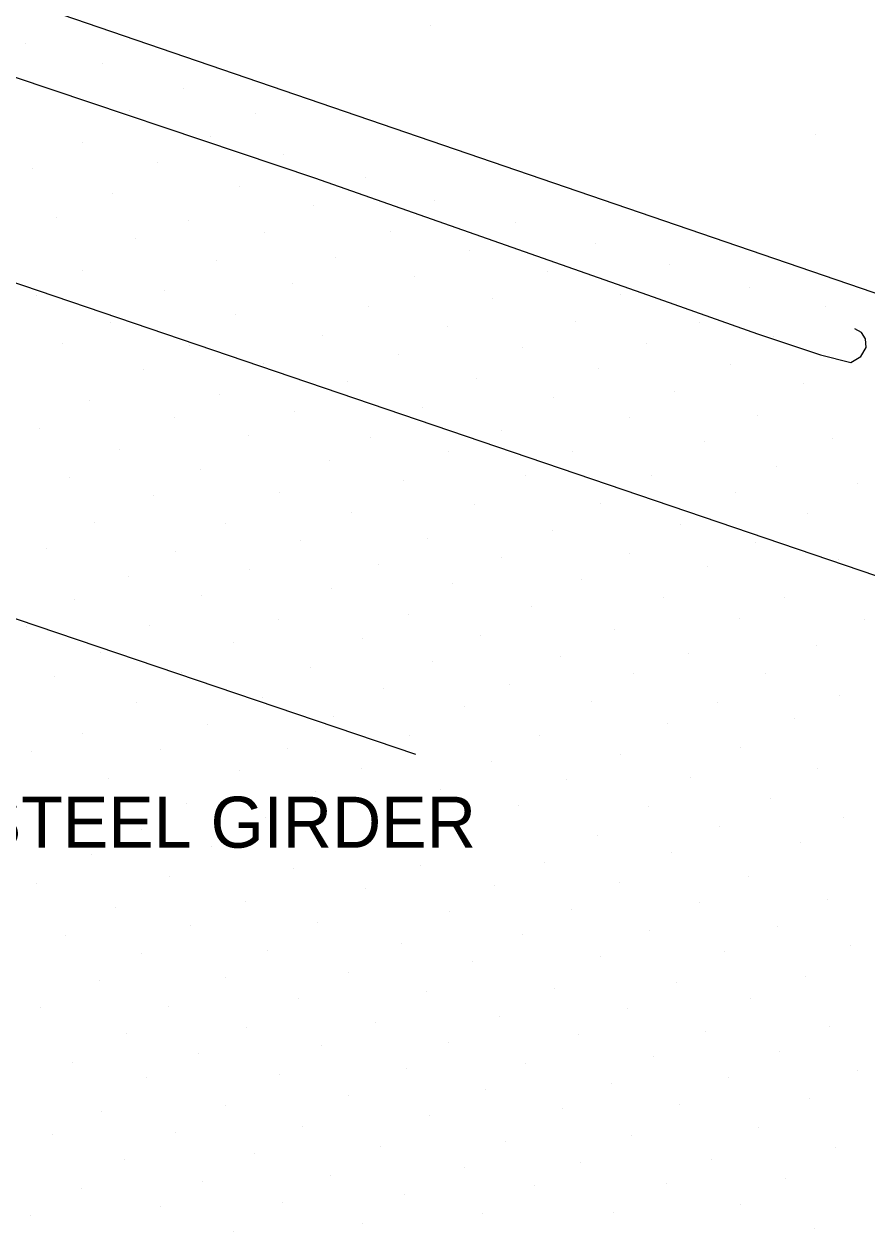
# Model space of a CAD drawing. Extents: x 1733582 to 1734070, y 467256 to 468256.
# Drawn here: x 1733864.11 to 1733893.84, y 467694.29 to 467736.94 of the extents above; entities that cross this region are included whole.
import ezdxf

# ---------------------------------------------------------------- set-up
doc = ezdxf.new("R2010")
doc.units = 0
for name, color, linetype in [('Default', 7, 'Continuous'), ('S_Ground_SpotElevation', 7, 'Continuous'), ('S_Guardrail_Beam', 7, 'Continuous'), ('S_Roadway_Edge_Pavement', 7, 'Continuous'), ('S_Roadway_Painted_Lines', 7, 'Continuous'), ('S_Text', 7, 'Continuous')]:
    doc.layers.add(name, color=color, linetype=linetype)

# ---------------------------------------------------------------- blocks, each defined once
blk = doc.blocks.new('POINT_DISPLAY')
at = {"layer": 'Default'}
blk.add_line((0, 0), (0, 0), dxfattribs=at)

msp = doc.modelspace()

# ---------------------------------------------------------------- linework, layer by layer
at = {"layer": 'S_Guardrail_Beam'}
msp.add_lwpolyline([(1733779.584, 467763.162), (1733791.412, 467759.266), (1733803.188, 467755.466), (1733815.088, 467751.54), (1733826.834, 467747.566), (1733839.025, 467743.476), (1733850.692, 467739.538), (1733862.451, 467735.523), (1733874.35, 467731.517), (1733886.109, 467727.39), (1733889.984, 467726.018), (1733892.208, 467725.279), (1733893.28, 467725.008), (1733893.637, 467725.214), (1733893.817, 467725.531), (1733893.796, 467725.839), (1733893.658, 467726.063), (1733893.419, 467726.195)], dxfattribs=at)
at = {"layer": 'S_Roadway_Edge_Pavement'}
msp.add_lwpolyline([(1734047.514, 467668.647), (1734012.708, 467681.197), (1733935.599, 467708.176), (1733908.807, 467722.422), (1733806.077, 467757.609), (1733715.329, 467786.896), (1733665.166, 467802.478), (1733604.388, 467822.173)], dxfattribs=at)
at = {"layer": 'S_Roadway_Painted_Lines'}
msp.add_line((1733862.631, 467716.356), (1733877.917, 467711.182), dxfattribs=at)
msp.add_lwpolyline([(1733600.615, 467812.285), (1733624.074, 467805.253), (1733650.091, 467797.478), (1733690.162, 467785.254), (1733709.513, 467779.192), (1733740.833, 467769.059), (1733764.442, 467761.384), (1733801.856, 467748.917), (1733825.1, 467741.003), (1733865.745, 467727.157), (1733942.114, 467701.157), (1734018.088, 467674.904), (1734046.328, 467664.849)], dxfattribs=at)

# ---------------------------------------------------------------- block references
at = {"layer": 'S_Ground_SpotElevation'}
for p in [(1733878.445, 467736.911), (1733864.142, 467736.245), (1733866.862, 467735.573), (1733869.723, 467734.67), (1733865.111, 467734.612), (1733867.837, 467733.88), (1733872.259, 467733.794), (1733870.681, 467732.986), (1733892.047, 467733.039), (1733866.165, 467732.756), (1733873.275, 467732.34), (1733864.402, 467731.852), (1733868.806, 467732.051), (1733876.138, 467731.541), (1733867.229, 467730.972), (1733871.722, 467731.199), (1733874.322, 467730.528), (1733878.578, 467730.719), (1733865.24, 467730.136), (1733869.903, 467730.024), (1733872.601, 467729.592), (1733877.033, 467729.637), (1733881.444, 467729.947), (1733868.044, 467729.391), (1733884.279, 467729.21), (1733875.11, 467728.692), (1733879.826, 467728.953), (1733870.879, 467728.612), (1733886.89, 467728.469), (1733866.184, 467728.237), (1733877.875, 467728.048), (1733882.563, 467728.212), (1733869.068, 467727.529), (1733873.562, 467727.786), (1733885.168, 467727.408), (1733889.688, 467727.659), (1733864.538, 467727.365), (1733876.272, 467726.984), (1733880.648, 467727.245), (1733892.376, 467726.977), (1733871.58, 467726.696), (1733867.16, 467726.427), (1733879.054, 467726.285), (1733883.581, 467726.456), (1733887.95, 467726.425), (1733874.651, 467725.966), (1733890.556, 467725.928), (1733865.461, 467725.688), (1733869.952, 467725.618), (1733877.32, 467725.289), (1733881.71, 467725.519), (1733886.07, 467725.683), (1733872.563, 467724.964), (1733889.037, 467724.921), (1733893.476, 467725.128), (1733868.327, 467724.774), (1733880.086, 467724.433), (1733884.359, 467724.804), (1733875.504, 467724.317), (1733891.613, 467724.263), (1733866.398, 467723.65), (1733870.989, 467723.873), (1733882.8, 467723.77), (1733887.05, 467723.971), (1733873.664, 467723.277), (1733878.162, 467723.404), (1733869.404, 467723.058), (1733885.452, 467723.062), (1733889.976, 467723.119), (1733864.653, 467722.688), (1733872.036, 467722.427), (1733876.321, 467722.37), (1733880.945, 467722.618), (1733892.638, 467722.336), (1733867.478, 467721.928), (1733879.09, 467721.866), (1733888.099, 467722.199), (1733874.887, 467721.528), (1733883.455, 467721.85), (1733870.347, 467721.214), (1733881.805, 467721.028), (1733886.254, 467721.021), (1733890.663, 467721.332), (1733865.718, 467720.957), (1733877.509, 467720.845), (1733893.527, 467720.718), (1733868.656, 467720.31), (1733873.127, 467720.416), (1733889.199, 467720.429), (1733879.996, 467719.984), (1733884.457, 467720.042), (1733866.588, 467719.349), (1733871.226, 467719.321), (1733875.647, 467719.696), (1733891.74, 467719.688), (1733882.751, 467719.058), (1733887.257, 467719.272), (1733873.877, 467718.711), (1733878.33, 467718.804), (1733889.922, 467718.666), (1733864.895, 467718.434), (1733869.46, 467718.342), (1733880.953, 467718.12), (1733885.469, 467718.272), (1733892.849, 467718.037), (1733872.068, 467717.692), (1733876.619, 467717.88), (1733888.232, 467717.818), (1733867.793, 467717.446), (1733879.241, 467717.199), (1733883.777, 467717.358), (1733870.377, 467716.786), (1733874.97, 467717.016), (1733865.896, 467716.639), (1733882.006, 467716.378), (1733886.652, 467716.72), (1733890.937, 467716.713), (1733873.095, 467715.948), (1733877.658, 467716.093), (1733889.34, 467715.962), (1733893.769, 467715.945), (1733864.19, 467715.7), (1733868.538, 467715.727), (1733884.942, 467715.566), (1733871.502, 467715.107), (1733876.041, 467715.264), (1733880.216, 467715.378), (1733866.804, 467714.758), (1733883.05, 467714.638), (1733887.536, 467714.74), (1733892.073, 467715.026), (1733874.227, 467714.248), (1733878.507, 467714.449), (1733865.18, 467713.931), (1733869.648, 467714.077), (1733885.625, 467714.02), (1733890.28, 467714.035), (1733876.786, 467713.488), (1733881.242, 467713.626), (1733868.09, 467713.013), (1733872.505, 467713.176), (1733884.124, 467713.046), (1733888.588, 467712.998), (1733892.869, 467713.238), (1733875.032, 467712.527), (1733879.655, 467712.875), (1733870.582, 467712.218), (1733886.813, 467712.275), (1733891.286, 467712.423), (1733866.152, 467711.924), (1733877.703, 467711.839), (1733882.281, 467711.855), (1733864.379, 467711.293), (1733868.905, 467711.335), (1733873.385, 467711.38), (1733889.39, 467711.424), (1733880.591, 467710.939), (1733885.162, 467711.173), (1733871.702, 467710.617), (1733876.019, 467710.69), (1733887.627, 467710.352), (1733892.116, 467710.686), (1733867.069, 467710.316), (1733878.784, 467709.932), (1733883.259, 467710.304), (1733874.376, 467709.876), (1733890.437, 467709.633), (1733865.421, 467709.459), (1733869.823, 467709.442), (1733881.543, 467709.383), (1733886.146, 467709.336), (1733872.614, 467708.956), (1733877.109, 467708.854), (1733893.014, 467708.943), (1733868.234, 467708.521), (1733879.654, 467708.315), (1733884.345, 467708.32), (1733888.655, 467708.623), (1733870.717, 467707.924), (1733875.206, 467708.122), (1733891.505, 467708.076), (1733866.501, 467707.636), (1733882.476, 467707.36), (1733886.964, 467707.703), (1733873.603, 467707.149), (1733878.095, 467707.249), (1733864.555, 467706.632), (1733869.25, 467706.857), (1733880.707, 467706.554), (1733885.107, 467706.656), (1733889.672, 467706.849), (1733876.163, 467706.44), (1733867.34, 467705.757), (1733871.929, 467705.973), (1733883.42, 467705.687), (1733887.948, 467705.932), (1733892.448, 467706.038), (1733874.458, 467705.23), (1733879.107, 467705.643), (1733869.971, 467705.119), (1733881.71, 467704.811), (1733886.17, 467704.948), (1733890.708, 467705.1), (1733865.554, 467704.786), (1733877.436, 467704.495), (1733893.266, 467704.416), (1733868.253, 467704.148), (1733872.69, 467704.265), (1733884.462, 467704.05), (1733888.819, 467704.224), (1733879.923, 467703.849), (1733866.784, 467703.197), (1733871.23, 467703.296), (1733875.564, 467703.488), (1733887.118, 467703.12), (1733891.689, 467703.33), (1733878.296, 467702.793), (1733882.818, 467702.911), (1733864.691, 467702.236), (1733869.206, 467702.288), (1733873.806, 467702.547), (1733889.748, 467702.569), (1733880.886, 467701.94), (1733885.401, 467702.19), (1733871.964, 467701.536), (1733876.494, 467701.695), (1733888.142, 467701.387), (1733892.525, 467701.588), (1733867.732, 467701.324), (1733879.098, 467701.01), (1733883.684, 467701.296), (1733870.263, 467700.623), (1733874.613, 467700.9), (1733890.751, 467700.682), (1733865.804, 467700.302), (1733881.787, 467700.276), (1733886.312, 467700.523), (1733868.437, 467699.766), (1733873.126, 467699.867), (1733877.614, 467700.08), (1733888.979, 467699.767), (1733893.519, 467700.003), (1733880.389, 467699.359), (1733884.828, 467699.544), (1733875.57, 467699.128), (1733891.825, 467699.026), (1733866.855, 467698.574), (1733871.223, 467698.785), (1733878.414, 467698.44), (1733883.123, 467698.671), (1733887.226, 467698.814), (1733873.92, 467698.045), (1733890.014, 467698.004), (1733865.105, 467697.748), (1733869.437, 467697.837), (1733885.547, 467697.707), (1733876.67, 467697.324), (1733881.078, 467697.512), (1733892.736, 467697.288), (1733867.654, 467696.885), (1733872.224, 467697.089), (1733883.75, 467696.768), (1733888.378, 467696.86), (1733874.931, 467696.298), (1733879.658, 467696.586), (1733866.118, 467695.859), (1733870.398, 467696.087), (1733882.104, 467695.951), (1733886.775, 467696.033), (1733890.974, 467696.217), (1733877.53, 467695.644), (1733868.932, 467695.217), (1733873.235, 467695.369), (1733884.896, 467694.993), (1733889.381, 467695.287), (1733864.348, 467694.894), (1733876.042, 467694.627), (1733880.284, 467694.957), (1733871.49, 467694.331), (1733891.994, 467694.439)]:
    msp.add_blockref('POINT_DISPLAY', p, dxfattribs=at)

# ---------------------------------------------------------------- texts
at = {"layer": 'S_Text'}
msp.add_text('BOT STEEL GIRDER', height=1.8, dxfattribs=at).set_placement((1733856.779, 467707.881))

doc.saveas('drawing.dxf')
